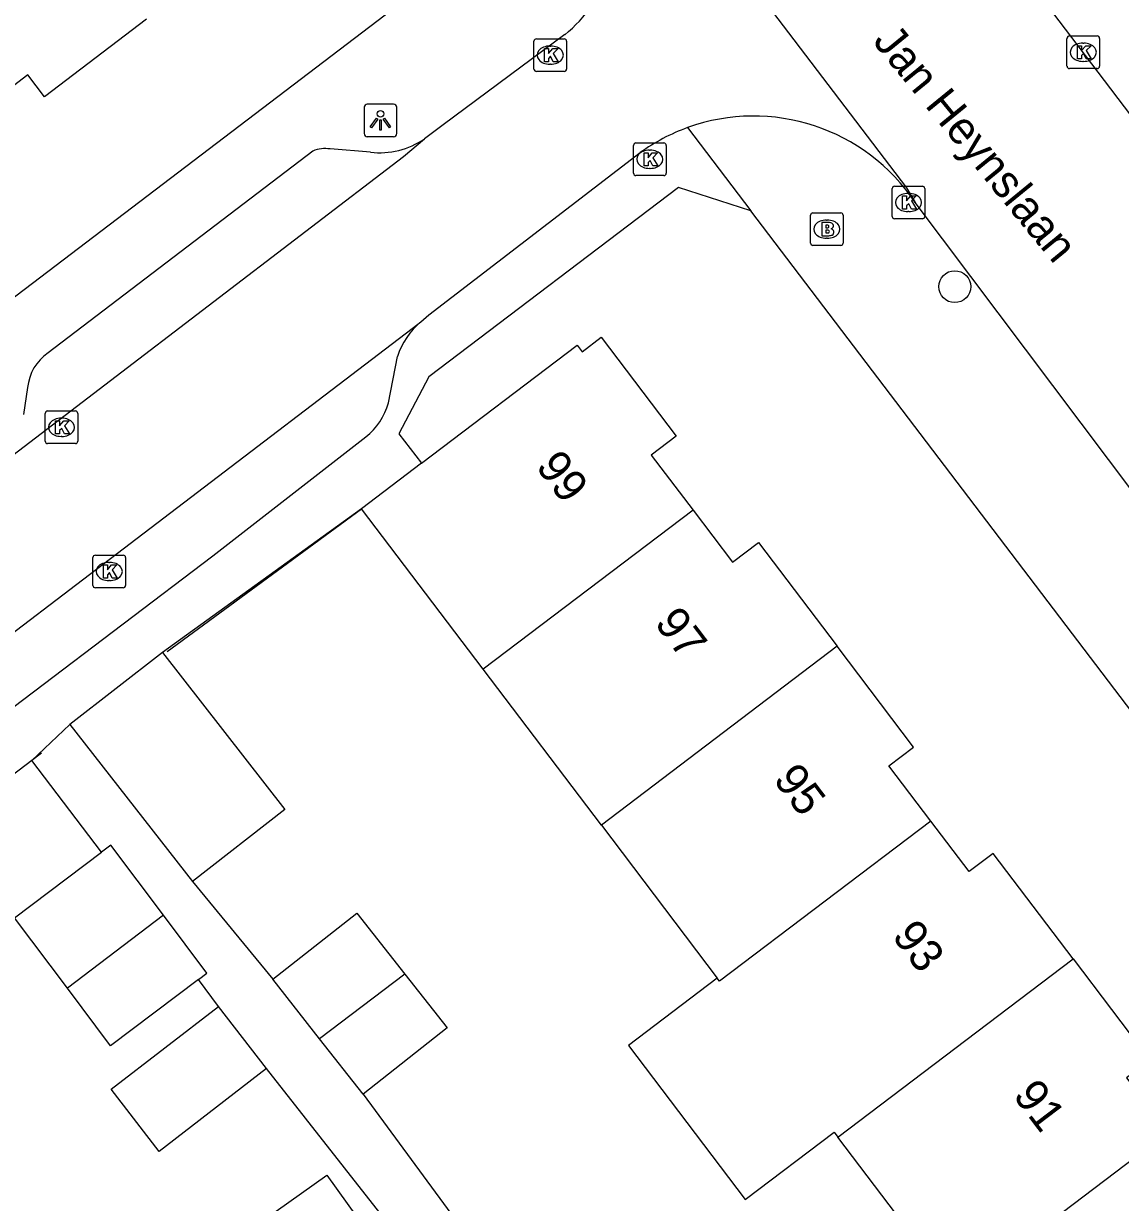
# Model space of a CAD drawing. Extents: x 160037 to 160839, y 385326 to 386441.
# Drawn here: x 160449.09 to 160482.72, y 385706.97 to 385743.1 of the extents above; entities that cross this region are included whole.
import ezdxf

# ---------------------------------------------------------------- set-up
doc = ezdxf.new("R2010")
doc.units = 0
for name, color, linetype in [('IMGEO_Boom', 7, 'Continuous'), ('IMGEO_Brandkraan', 7, 'Continuous'), ('IMGEO_Kolk', 7, 'Continuous'), ('IMGEO_Lichtpunt', 7, 'Continuous'), ('IMGEO_Muur', 7, 'Continuous'), ('IMGEO_Openbare_ruimte_label', 7, 'Continuous'), ('IMGEO_Pand', 7, 'Continuous'), ('IMGEO_Pand_nummerreeks', 7, 'Continuous'), ('IMGEO_Rijbaan_lokaal_open', 7, 'Continuous'), ('IMGEO_Voetpad_open', 7, 'Continuous')]:
    doc.layers.add(name, color=color, linetype=linetype)

msp = doc.modelspace()

# ---------------------------------------------------------------- linework, layer by layer
at = {"layer": 'IMGEO_Boom'}
msp.add_circle((160477.639, 385735.035), 0.489, dxfattribs=at)
at = {"layer": 'IMGEO_Brandkraan'}
for p, q in [((160473.292, 385737.297), (160474.144, 385737.297)), ((160473.217, 385736.371), (160473.217, 385737.223)), ((160473.705, 385737.077), (160473.73, 385737.077)), ((160474.218, 385737.223), (160474.218, 385736.371)), ((160474.144, 385736.297), (160473.292, 385736.297)), ((160473.728, 385736.517), (160473.703, 385736.517))]:
    msp.add_line(p, q, dxfattribs=at)
for points in [[(160473.292, 385737.297), (160474.144, 385737.297)], [(160473.217, 385736.371), (160473.217, 385737.223)], [(160473.565, 385736.997), (160473.565, 385736.597), (160473.778, 385736.597)], [(160473.796, 385736.997), (160473.565, 385736.997)], [(160474.218, 385737.223), (160474.218, 385736.371)], [(160473.744, 385736.916), (160473.69, 385736.916), (160473.69, 385736.84)], [(160473.69, 385736.84), (160473.743, 385736.84)], [(160473.752, 385736.764), (160473.69, 385736.764), (160473.69, 385736.683)], [(160473.69, 385736.683), (160473.752, 385736.683)], [(160474.144, 385736.297), (160473.292, 385736.297)]]:
    msp.add_lwpolyline(points, dxfattribs=at)
for centre, radius, start, end in [((160473.294, 385737.221), 0.0765, 91.552, 178.448), ((160473.294, 385737.221), 0.0765, 91.552, 178.448), ((160474.142, 385737.221), 0.0765, 1.552, 88.448), ((160474.142, 385737.221), 0.0765, 1.552, 88.448), ((160473.8, 385736.852), 0.145, 59.4692, 91.5367), ((160473.825, 385736.899), 0.0922, 285.5137, 58.1501), ((160473.745, 385736.878), 0.0379, 267.8285, 90.9355), ((160473.753, 385736.723), 0.0404, 269.8759, 90.5077), ((160473.784, 385736.848), 0.251, 268.6676, 293.5347), ((160473.83, 385736.707), 0.105, 301.3115, 78.989), ((160473.294, 385736.373), 0.0765, 181.552, 268.448), ((160473.294, 385736.373), 0.0765, 181.552, 268.448), ((160474.142, 385736.373), 0.0765, 271.552, 358.448), ((160474.142, 385736.373), 0.0765, 271.552, 358.448)]:
    msp.add_arc(centre, radius, start, end, dxfattribs=at)
for centre, major_axis, ratio, start_param, end_param in [((160473.704, 385736.797), (-0.387, 0.002), 0.722429, 4.712389, 7.853982), ((160473.729, 385736.797), (-0.39, 0.002), 0.717154, 1.570796, 4.712389)]:
    msp.add_ellipse(centre, major_axis=major_axis, ratio=ratio, start_param=start_param, end_param=end_param, dxfattribs=at)
at = {"layer": 'IMGEO_Kolk'}
for p, q in [((160481.154, 385742.719), (160482.006, 385742.719)), ((160464.738, 385741.704), (160464.738, 385742.556)), ((160464.813, 385742.63), (160465.665, 385742.63)), ((160465.226, 385742.41), (160465.251, 385742.41)), ((160465.739, 385742.556), (160465.739, 385741.704)), ((160481.079, 385741.793), (160481.079, 385742.645)), ((160481.567, 385742.499), (160481.592, 385742.499)), ((160482.08, 385742.645), (160482.08, 385741.793)), ((160465.249, 385741.85), (160465.224, 385741.85)), ((160482.006, 385741.719), (160481.154, 385741.719)), ((160481.59, 385741.939), (160481.565, 385741.939)), ((160465.665, 385741.63), (160464.813, 385741.63)), ((160467.791, 385738.513), (160467.791, 385739.365)), ((160467.866, 385739.439), (160468.718, 385739.439)), ((160468.279, 385739.219), (160468.304, 385739.219)), ((160468.792, 385739.365), (160468.792, 385738.513)), ((160468.718, 385738.439), (160467.866, 385738.439)), ((160468.302, 385738.659), (160468.277, 385738.659)), ((160475.718, 385737.188), (160475.718, 385738.04)), ((160475.793, 385738.114), (160476.645, 385738.114)), ((160476.719, 385738.04), (160476.719, 385737.188)), ((160476.206, 385737.894), (160476.231, 385737.894)), ((160476.229, 385737.334), (160476.204, 385737.334)), ((160476.645, 385737.114), (160475.793, 385737.114)), ((160449.828, 385731.225), (160450.68, 385731.225)), ((160449.753, 385730.299), (160449.753, 385731.151)), ((160450.241, 385731.005), (160450.266, 385731.005)), ((160450.754, 385731.151), (160450.754, 385730.299)), ((160450.264, 385730.445), (160450.239, 385730.445)), ((160450.68, 385730.225), (160449.828, 385730.225)), ((160451.217, 385725.88), (160451.217, 385726.732)), ((160451.292, 385726.806), (160452.144, 385726.806)), ((160451.705, 385726.586), (160451.73, 385726.586)), ((160452.218, 385726.732), (160452.218, 385725.88)), ((160452.144, 385725.806), (160451.292, 385725.806)), ((160451.728, 385726.026), (160451.703, 385726.026))]:
    msp.add_line(p, q, dxfattribs=at)
for points in [[(160481.154, 385742.719), (160482.006, 385742.719)], [(160464.738, 385741.704), (160464.738, 385742.556)], [(160464.813, 385742.63), (160465.665, 385742.63)], [(160465.739, 385742.556), (160465.739, 385741.704)], [(160481.079, 385741.793), (160481.079, 385742.645)], [(160481.4, 385742.419), (160481.523, 385742.419), (160481.523, 385742.268), (160481.653, 385742.419), (160481.817, 385742.419), (160481.671, 385742.268), (160481.824, 385742.019), (160481.672, 385742.019), (160481.587, 385742.183), (160481.523, 385742.116), (160481.523, 385742.019), (160481.4, 385742.019), (160481.4, 385742.419)], [(160482.08, 385742.645), (160482.08, 385741.793)], [(160465.059, 385742.33), (160465.182, 385742.33), (160465.182, 385742.179), (160465.312, 385742.33), (160465.476, 385742.33), (160465.33, 385742.179), (160465.483, 385741.93), (160465.331, 385741.93), (160465.246, 385742.094), (160465.182, 385742.027), (160465.182, 385741.93), (160465.059, 385741.93), (160465.059, 385742.33)], [(160482.006, 385741.719), (160481.154, 385741.719)], [(160465.665, 385741.63), (160464.813, 385741.63)], [(160467.791, 385738.513), (160467.791, 385739.365)], [(160467.866, 385739.439), (160468.718, 385739.439)], [(160468.112, 385739.139), (160468.235, 385739.139), (160468.235, 385738.988), (160468.365, 385739.139), (160468.529, 385739.139), (160468.383, 385738.988), (160468.536, 385738.739), (160468.384, 385738.739), (160468.299, 385738.903), (160468.235, 385738.836), (160468.235, 385738.739), (160468.112, 385738.739), (160468.112, 385739.139)], [(160468.792, 385739.365), (160468.792, 385738.513)], [(160468.718, 385738.439), (160467.866, 385738.439)], [(160475.718, 385737.188), (160475.718, 385738.04)], [(160475.793, 385738.114), (160476.645, 385738.114)], [(160476.719, 385738.04), (160476.719, 385737.188)], [(160476.039, 385737.814), (160476.162, 385737.814), (160476.162, 385737.663), (160476.292, 385737.814), (160476.456, 385737.814), (160476.31, 385737.663), (160476.463, 385737.414), (160476.311, 385737.414), (160476.226, 385737.578), (160476.162, 385737.511), (160476.162, 385737.414), (160476.039, 385737.414), (160476.039, 385737.814)], [(160476.645, 385737.114), (160475.793, 385737.114)], [(160449.828, 385731.225), (160450.68, 385731.225)], [(160449.753, 385730.299), (160449.753, 385731.151)], [(160450.074, 385730.925), (160450.197, 385730.925), (160450.197, 385730.774), (160450.327, 385730.925), (160450.491, 385730.925), (160450.345, 385730.774), (160450.498, 385730.525), (160450.346, 385730.525), (160450.261, 385730.689), (160450.197, 385730.622), (160450.197, 385730.525), (160450.074, 385730.525), (160450.074, 385730.925)], [(160450.754, 385731.151), (160450.754, 385730.299)], [(160450.68, 385730.225), (160449.828, 385730.225)], [(160451.217, 385725.88), (160451.217, 385726.732)], [(160451.292, 385726.806), (160452.144, 385726.806)], [(160451.538, 385726.506), (160451.661, 385726.506), (160451.661, 385726.355), (160451.791, 385726.506), (160451.955, 385726.506), (160451.809, 385726.355), (160451.962, 385726.106), (160451.81, 385726.106), (160451.725, 385726.27), (160451.661, 385726.203), (160451.661, 385726.106), (160451.538, 385726.106), (160451.538, 385726.506)], [(160452.218, 385726.732), (160452.218, 385725.88)], [(160452.144, 385725.806), (160451.292, 385725.806)]]:
    msp.add_lwpolyline(points, dxfattribs=at)
for centre, start, end in [((160481.156, 385742.643), 91.552, 178.448), ((160481.156, 385742.643), 91.552, 178.448), ((160482.004, 385742.643), 1.552, 88.448), ((160482.004, 385742.643), 1.552, 88.448), ((160464.815, 385742.554), 91.552, 178.448), ((160464.815, 385742.554), 91.552, 178.448), ((160465.663, 385742.554), 1.552, 88.448), ((160465.663, 385742.554), 1.552, 88.448), ((160464.815, 385741.706), 181.552, 268.448), ((160464.815, 385741.706), 181.552, 268.448), ((160465.663, 385741.706), 271.552, 358.448), ((160465.663, 385741.706), 271.552, 358.448), ((160481.156, 385741.795), 181.552, 268.448), ((160481.156, 385741.795), 181.552, 268.448), ((160482.004, 385741.795), 271.552, 358.448), ((160482.004, 385741.795), 271.552, 358.448), ((160467.868, 385739.363), 91.552, 178.448), ((160467.868, 385739.363), 91.552, 178.448), ((160468.716, 385739.363), 1.552, 88.448), ((160468.716, 385739.363), 1.552, 88.448), ((160467.868, 385738.515), 181.552, 268.448), ((160467.868, 385738.515), 181.552, 268.448), ((160468.716, 385738.515), 271.552, 358.448), ((160468.716, 385738.515), 271.552, 358.448), ((160475.795, 385738.038), 91.552, 178.448), ((160475.795, 385738.038), 91.552, 178.448), ((160476.643, 385738.038), 1.552, 88.448), ((160476.643, 385738.038), 1.552, 88.448), ((160475.795, 385737.19), 181.552, 268.448), ((160475.795, 385737.19), 181.552, 268.448), ((160476.643, 385737.19), 271.552, 358.448), ((160476.643, 385737.19), 271.552, 358.448), ((160449.83, 385731.149), 91.552, 178.448), ((160449.83, 385731.149), 91.552, 178.448), ((160450.678, 385731.149), 1.552, 88.448), ((160450.678, 385731.149), 1.552, 88.448), ((160449.83, 385730.301), 181.552, 268.448), ((160449.83, 385730.301), 181.552, 268.448), ((160450.678, 385730.301), 271.552, 358.448), ((160450.678, 385730.301), 271.552, 358.448), ((160451.294, 385726.73), 91.552, 178.448), ((160451.294, 385726.73), 91.552, 178.448), ((160452.142, 385726.73), 1.552, 88.448), ((160452.142, 385726.73), 1.552, 88.448), ((160451.294, 385725.882), 181.552, 268.448), ((160451.294, 385725.882), 181.552, 268.448), ((160452.142, 385725.882), 271.552, 358.448), ((160452.142, 385725.882), 271.552, 358.448)]:
    msp.add_arc(centre, 0.0765, start, end, dxfattribs=at)
for centre, major_axis, ratio, start_param, end_param in [((160465.225, 385742.13), (-0.387, 0.002), 0.722429, 4.712389, 7.853982), ((160465.25, 385742.13), (-0.39, 0.002), 0.717154, 1.570796, 4.712389), ((160481.566, 385742.219), (-0.387, 0.002), 0.722429, 4.712389, 7.853982), ((160481.591, 385742.219), (-0.39, 0.002), 0.717154, 1.570796, 4.712389), ((160468.278, 385738.939), (-0.387, 0.002), 0.722429, 4.712389, 7.853982), ((160468.303, 385738.939), (-0.39, 0.002), 0.717154, 1.570796, 4.712389), ((160476.205, 385737.614), (-0.387, 0.002), 0.722429, 4.712389, 7.853982), ((160476.23, 385737.614), (-0.39, 0.002), 0.717154, 1.570796, 4.712389), ((160450.24, 385730.725), (-0.387, 0.002), 0.722429, 4.712389, 7.853982), ((160450.265, 385730.725), (-0.39, 0.002), 0.717154, 1.570796, 4.712389), ((160451.704, 385726.306), (-0.387, 0.002), 0.722429, 4.712389, 7.853982), ((160451.729, 385726.306), (-0.39, 0.002), 0.717154, 1.570796, 4.712389)]:
    msp.add_ellipse(centre, major_axis=major_axis, ratio=ratio, start_param=start_param, end_param=end_param, dxfattribs=at)
at = {"layer": 'IMGEO_Lichtpunt'}
for p, q in [((160460.436, 385740.628), (160459.628, 385740.628)), ((160460.436, 385740.628), (160459.628, 385740.628)), ((160459.534, 385740.533), (160459.534, 385739.726)), ((160459.534, 385740.533), (160459.534, 385739.726)), ((160460.53, 385739.726), (160460.53, 385740.533)), ((160460.53, 385739.726), (160460.53, 385740.533)), ((160459.628, 385739.632), (160460.436, 385739.632)), ((160459.628, 385739.632), (160460.436, 385739.632))]:
    msp.add_line(p, q, dxfattribs=at)
for points in [[(160459.908, 385740.197), (160459.947, 385740.169), (160459.759, 385739.907), (160459.721, 385739.934), (160459.908, 385740.197)], [(160460.12, 385740.169), (160460.158, 385740.196), (160460.345, 385739.934), (160460.306, 385739.906), (160460.12, 385740.169)], [(160460.01, 385740.149), (160460.057, 385740.149), (160460.057, 385739.827), (160460.01, 385739.827), (160460.01, 385740.149)]]:
    msp.add_lwpolyline(points, dxfattribs=at)
msp.add_circle((160460.033, 385740.331), 0.0994, dxfattribs=at)
for centre, start, end in [((160459.628, 385740.533), 90, 180), ((160459.628, 385740.533), 90, 180), ((160460.436, 385740.533), 0, 90), ((160460.436, 385740.533), 0, 90), ((160459.628, 385739.726), 180, 270), ((160459.628, 385739.726), 180, 270), ((160460.436, 385739.726), 270, 0), ((160460.436, 385739.726), 270, 360)]:
    msp.add_arc(centre, 0.0946, start, end, dxfattribs=at)
at = {"layer": 'IMGEO_Muur'}
for points in [[(160453.489, 385723.856), (160459.454, 385728.228)], [(160449.644, 385720.741), (160449.342, 385720.511), (160440.682, 385713.917)]]:
    msp.add_lwpolyline(points, dxfattribs=at)
at = {"layer": 'IMGEO_Pand'}
for points in [[(160452.864, 385743.228), (160449.736, 385740.849), (160449.223, 385741.523), (160447.575, 385740.27)], [(160461.292, 385729.622), (160466.062, 385733.238), (160466.214, 385733.037), (160466.801, 385733.482), (160469.098, 385730.452), (160468.336, 385729.875), (160469.615, 385728.189)], [(160461.292, 385729.622), (160459.454, 385728.228)], [(160463.181, 385723.311), (160459.454, 385728.228)], [(160469.615, 385728.189), (160463.181, 385723.311)], [(160469.615, 385728.189), (160470.827, 385726.59), (160471.624, 385727.194), (160474.037, 385724.012)], [(160474.037, 385724.012), (160466.806, 385718.53)], [(160476.904, 385718.656), (160475.62, 385720.351), (160476.377, 385720.925), (160474.037, 385724.012)], [(160453.348, 385723.824), (160450.514, 385721.616)], [(160453.348, 385723.824), (160457.101, 385719.01), (160454.267, 385716.802)], [(160466.806, 385718.53), (160463.181, 385723.311)], [(160450.514, 385721.616), (160454.267, 385716.802)], [(160466.806, 385718.53), (160470.356, 385713.847)], [(160476.904, 385718.656), (160470.431, 385713.748), (160470.356, 385713.847)], [(160481.265, 385714.434), (160478.815, 385717.666), (160478.078, 385717.108), (160476.904, 385718.656)], [(160453.378, 385715.769), (160451.766, 385717.915), (160451.482, 385717.701)], [(160450.438, 385713.531), (160448.812, 385715.696), (160451.482, 385717.701)], [(160453.378, 385715.769), (160450.438, 385713.531)], [(160454.456, 385713.798), (160454.713, 385713.991), (160453.378, 385715.769)], [(160456.728, 385713.808), (160459.306, 385715.837), (160460.781, 385713.962)], [(160474.055, 385708.967), (160481.265, 385714.434)], [(160481.265, 385714.434), (160483.618, 385711.33), (160482.905, 385710.789), (160484.177, 385709.11)], [(160460.781, 385713.962), (160458.166, 385711.98)], [(160460.781, 385713.962), (160462.076, 385712.316), (160459.498, 385710.288)], [(160470.356, 385713.847), (160467.633, 385711.782), (160471.214, 385707.058), (160473.937, 385709.122), (160474.055, 385708.967)], [(160454.456, 385713.798), (160451.759, 385711.772), (160450.438, 385713.531)], [(160458.166, 385711.98), (160456.728, 385713.808)], [(160456.543, 385711.069), (160453.248, 385708.53), (160451.777, 385710.438), (160455.072, 385712.977)], [(160456.543, 385711.069), (160455.072, 385712.977)], [(160459.498, 385710.288), (160458.166, 385711.98)], [(160477.68, 385704.185), (160474.055, 385708.967)], [(160484.177, 385709.11), (160477.68, 385704.185)], [(160457.643, 385703.932), (160456.062, 385706.145), (160458.39, 385707.808), (160459.92, 385705.665)]]:
    msp.add_lwpolyline(points, dxfattribs=at)
at = {"layer": 'IMGEO_Rijbaan_lokaal_open'}
for points in [[(160490.796, 385730.087), (160475.667, 385750), (160461.3, 385768.906)], [(160466.313, 385750.996), (160466.344, 385750.961), (160476.157, 385738.065), (160476.427, 385737.611)], [(160465.684, 385742.758), (160461.953, 385739.99), (160461.382, 385739.566)], [(160442.926, 385725.336), (160448.737, 385729.856), (160448.762, 385729.875), (160460.742, 385739.019), (160461.382, 385739.566)], [(160461.267, 385733.959), (160461.519, 385734.173), (160467.994, 385739.142)], [(160500.083, 385706.193), (160500, 385706.302), (160498.422, 385708.377), (160476.427, 385737.611)], [(160445.5, 385721.947), (160445.769, 385722.152), (160461, 385733.756), (160461.267, 385733.959)]]:
    msp.add_lwpolyline(points, dxfattribs=at)
for centre, radius, start, end in [((160462.943, 385746.146), 4.358, 308.9703, 341.1351), ((160471.472, 385734.31), 5.954, 33.6706, 109.8836), ((160471.469, 385734.318), 5.945, 109.886, 125.7708)]:
    msp.add_arc(centre, radius, start, end, dxfattribs=at)
at = {"layer": 'IMGEO_Voetpad_open'}
for points in [[(160440.882, 385659.407), (160407.478, 385703.294), (160463, 385745.517)], [(160469.447, 385739.909), (160471.388, 385737.358)], [(160457.962, 385739.189), (160449.842, 385733.004)], [(160459.728, 385739.157), (160458.488, 385739.254)], [(160471.388, 385737.358), (160469.17, 385738.072), (160461.513, 385732.273), (160460.598, 385730.527), (160461.292, 385729.622)], [(160533.41, 385655.858), (160500, 385699.746), (160471.388, 385737.358)], [(160460.275, 385731.478), (160460.552, 385732.898)], [(160449.213, 385731.941), (160449.091, 385731.113)], [(160446.64, 385720.537), (160454.889, 385726.781), (160459.579, 385730.435)], [(160459.454, 385728.228), (160453.348, 385723.824)], [(160450.514, 385721.616), (160449.342, 385720.511)], [(160449.342, 385720.511), (160440.682, 385713.917)], [(160451.482, 385717.701), (160449.342, 385720.511)], [(160454.267, 385716.802), (160456.728, 385713.808)], [(160455.072, 385712.977), (160454.456, 385713.798)], [(160466.219, 385698.757), (160456.543, 385711.069)], [(160459.498, 385710.288), (160463.8, 385704.437)]]:
    msp.add_lwpolyline(points, dxfattribs=at)
for centre, radius, start, end in [((160460.023, 385741.511), 2.372, 262.8451, 304.9338), ((160458.327, 385738.399), 0.87, 79.3201, 114.769), ((160462.895, 385732.09), 2.479, 131.0681, 160.9804), ((160450.671, 385731.796), 1.465, 124.461, 174.3116), ((160458.43, 385731.955), 1.906, 307.0781, 345.4911)]:
    msp.add_arc(centre, radius, start, end, dxfattribs=at)

# ---------------------------------------------------------------- texts
at = {"layer": 'IMGEO_Openbare_ruimte_label'}
msp.add_text('Jan Heynslaan', height=1, rotation=309.2773, dxfattribs=at).set_placement((160475.099, 385742.542))
at = {"layer": 'IMGEO_Pand_nummerreeks'}
for s, rotation, p in [('99', 307.1959, (160464.77, 385729.516)), ('97', 307.1959, (160468.41, 385724.719)), ('95', 307.1962, (160472.05, 385719.923)), ('93', 307.1962, (160475.69, 385715.127)), ('91', 307.1959, (160479.399, 385710.24))]:
    msp.add_text(s, height=1, rotation=rotation, dxfattribs=at).set_placement(p)

doc.saveas('drawing.dxf')
